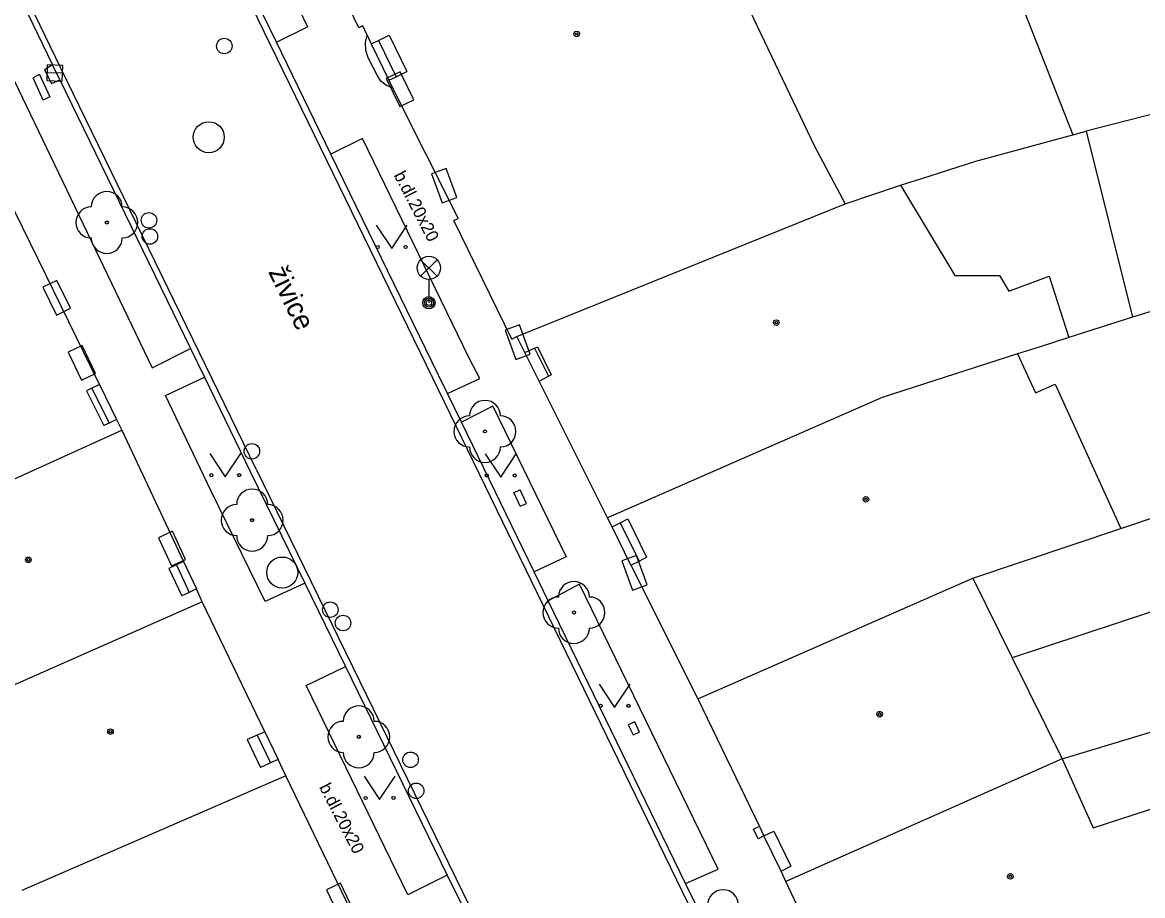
# Model space of a CAD drawing. Extents: x -595546 to -593986, y -1160845 to -1159202.
# Drawn here: x -595474.42 to -595438.29, y -1160132.09 to -1160103.93 of the extents above; entities that cross this region are included whole.
import ezdxf

# ---------------------------------------------------------------- set-up
doc = ezdxf.new("R2010")
doc.units = 0
for name, color, linetype in [('DOP - rozhrani ploch obecne', 7, 'Continuous'), ('Level 22', 7, 'Continuous'), ('Level 24', 7, 'Continuous'), ('Level 27', 7, 'Continuous'), ('Level 28', 7, 'Continuous'), ('Level 31', 7, 'Continuous'), ('Level 33', 7, 'Continuous'), ('Level 36', 7, 'Continuous'), ('Level 39', 7, 'Continuous'), ('silnoproud - povrch.  znaky a  RIS  skut. velikost', 7, 'Continuous'), ('slaboproud - povrch.  znaky a tel. budka skut. velikost', 7, 'Continuous'), ('TM - budovy zdene_ betonove - NP', 7, 'Continuous'), ('TM - budovy zdene_ betonove - VP', 7, 'Continuous'), ('TM - chodniky - VP', 7, 'Continuous'), ('TM - komunikace - VP', 7, 'Continuous'), ('TM - letecke snimky - pomocna linie', 7, 'Continuous'), ('TM - pomocna konstrukcni linie', 7, 'Continuous'), ('TM - popis povrchu', 7, 'Continuous'), ('TM - rozhrani mezi zpev. plochami mezi sebou - VP', 7, 'Continuous'), ('TM - rozhrani ploch obecne - VP', 7, 'Continuous'), ('TM - schody - NP', 7, 'Continuous'), ('TM - vstup do budovy - zdene_ betonove', 7, 'Continuous')]:
    doc.layers.add(name, color=color, linetype=linetype)

msp = doc.modelspace()

# ---------------------------------------------------------------- linework, layer by layer
at = {"layer": 'DOP - rozhrani ploch obecne'}
for points in [[(-595432.28, -1160105.44), (-595438.3, -1160106.97), (-595440.11, -1160107.43)], [(-595440.54, -1160107.55), (-595440.11, -1160107.43)], [(-595440.11, -1160107.43), (-595438.61, -1160113.43)], [(-595443.67, -1160108.4), (-595440.54, -1160107.55)], [(-595446.09, -1160109.18), (-595445.41, -1160108.96), (-595443.67, -1160108.4)], [(-595437.7, -1160113.16), (-595438.61, -1160113.43)], [(-595438.61, -1160113.43), (-595440.66, -1160114.09)], [(-595438.99, -1160120.25), (-595435.12, -1160118.95)]]:
    msp.add_lwpolyline(points, dxfattribs=at)
at = {"layer": 'Level 22'}
for centre in [(-595471.7, -1160110.38), (-595459.5, -1160117.12), (-595467.01, -1160119.98), (-595456.63, -1160122.96), (-595463.57, -1160126.97)]:
    msp.add_circle(centre, 0.05, dxfattribs=at)
for centre, start, end in [((-595471.7, -1160109.88), 0, 180), ((-595472.2, -1160110.38), 90, 270), ((-595471.2, -1160110.38), 270, 90), ((-595471.7, -1160110.88), 180, 0), ((-595459.5, -1160116.62), 0, 180), ((-595460, -1160117.12), 90, 270), ((-595459, -1160117.12), 270, 90), ((-595459.5, -1160117.62), 180, 0), ((-595467.01, -1160119.48), 0, 180), ((-595467.51, -1160119.98), 90, 270), ((-595466.51, -1160119.98), 270, 90), ((-595467.01, -1160120.48), 180, 0), ((-595456.63, -1160122.46), 0, 180), ((-595457.13, -1160122.96), 90, 270), ((-595456.13, -1160122.96), 270, 90), ((-595456.63, -1160123.46), 180, 0), ((-595463.57, -1160126.47), 0, 180), ((-595464.07, -1160126.97), 90, 270), ((-595463.07, -1160126.97), 270, 90), ((-595463.57, -1160127.47), 180, 0), ((-595451.82, -1160132.4), 0, 180)]:
    msp.add_arc(centre, 0.5, start, end, dxfattribs=at)
at = {"layer": 'Level 24'}
for points in [[(-595462.686, -1160105.741), (-595462.249, -1160106.64), (-595461.799, -1160106.421), (-595462.237, -1160105.522)], [(-595461.221, -1160108.806), (-595460.879, -1160109.746), (-595460.409, -1160109.575), (-595460.751, -1160108.635)], [(-595472.872, -1160113.149), (-595473.31, -1160112.251), (-595473.76, -1160112.47), (-595473.321, -1160113.369)], [(-595458.851, -1160113.856), (-595458.509, -1160114.796), (-595458.039, -1160114.625), (-595458.381, -1160113.685)], [(-595472.943, -1160114.567), (-595472.513, -1160115.47), (-595472.062, -1160115.255), (-595472.492, -1160114.352)], [(-595469.158, -1160121.245), (-595469.584, -1160120.34), (-595470.036, -1160120.553), (-595469.611, -1160121.458)], [(-595455.081, -1160121.296), (-595454.739, -1160122.236), (-595454.269, -1160122.065), (-595454.611, -1160121.125)], [(-595463.726, -1160132.593), (-595464.157, -1160131.69), (-595464.608, -1160131.905), (-595464.178, -1160132.808)]]:
    msp.add_lwpolyline(points, close=True, dxfattribs=at)
at = {"layer": 'Level 27'}
msp.add_line((-595473.13, -1160105.569), (-595473.63, -1160105.551), dxfattribs=at)
msp.add_lwpolyline([(-595473.121, -1160105.319), (-595473.621, -1160105.301), (-595473.639, -1160105.801), (-595473.139, -1160105.819)], close=True, dxfattribs=at)
for centre in [(-595468.41, -1160107.63), (-595466.04, -1160121.67)]:
    msp.add_circle(centre, 0.5, dxfattribs=at)
at = {"layer": 'Level 28'}
for centre in [(-595470.34, -1160110.31), (-595470.31, -1160110.83), (-595467.02, -1160117.76), (-595464.49, -1160122.87), (-595464.08, -1160123.3), (-595461.9, -1160127.71), (-595461.72, -1160128.71)]:
    msp.add_circle(centre, 0.25, dxfattribs=at)
at = {"layer": 'Level 31'}
msp.add_circle((-595467.91, -1160104.69), 0.25, dxfattribs=at)
at = {"layer": 'Level 33'}
for p, q in [((-595461.575, -1160112.11), (-595461.045, -1160111.58)), ((-595461.575, -1160111.58), (-595461.045, -1160112.11)), ((-595461.31, -1160112.22), (-595461.31, -1160112.97))]:
    msp.add_line(p, q, dxfattribs=at)
for centre, radius in [((-595461.31, -1160111.845), 0.375), ((-595461.31, -1160112.97), 0.2), ((-595461.31, -1160112.97), 0.145), ((-595461.31, -1160112.97), 0.0876)]:
    msp.add_circle(centre, radius, dxfattribs=at)
at = {"layer": 'Level 36'}
for points in [[(-595463.01, -1160110.47), (-595462.51, -1160111.22), (-595462.01, -1160110.47)], [(-595468.38, -1160117.83), (-595467.88, -1160118.58), (-595467.38, -1160117.83)], [(-595459.49, -1160117.84), (-595458.99, -1160118.59), (-595458.49, -1160117.84)], [(-595455.82, -1160125.27), (-595455.32, -1160126.02), (-595454.82, -1160125.27)], [(-595463.4, -1160128.24), (-595462.9, -1160128.99), (-595462.4, -1160128.24)]]:
    msp.add_lwpolyline(points, dxfattribs=at)
for centre in [(-595462.96, -1160111.17), (-595462.061, -1160111.17), (-595468.33, -1160118.53), (-595467.431, -1160118.53), (-595459.44, -1160118.54), (-595458.541, -1160118.54), (-595455.77, -1160125.97), (-595454.871, -1160125.97), (-595463.35, -1160128.94), (-595462.451, -1160128.94)]:
    msp.add_circle(centre, 0.05, dxfattribs=at)
at = {"layer": 'Level 39'}
for centre, radius in [((-595456.54, -1160104.3), 0.09), ((-595456.54, -1160104.3), 0.0398), ((-595450.1, -1160113.61), 0.09), ((-595450.1, -1160113.61), 0.0398), ((-595447.21, -1160119.31), 0.09), ((-595447.21, -1160119.31), 0.0398), ((-595474.23, -1160121.26), 0.09), ((-595474.23, -1160121.26), 0.0398), ((-595446.77, -1160126.24), 0.09), ((-595446.77, -1160126.24), 0.0398), ((-595471.58, -1160126.8), 0.09), ((-595471.58, -1160126.8), 0.0398), ((-595442.55, -1160131.47), 0.09), ((-595442.55, -1160131.47), 0.0398)]:
    msp.add_circle(centre, radius, dxfattribs=at)
at = {"layer": 'silnoproud - povrch.  znaky a  RIS  skut. velikost'}
for points in [[(-595458.57, -1160119.09), (-595458.36, -1160119)], [(-595458.16, -1160119.44), (-595458.36, -1160119)], [(-595458.37, -1160119.53), (-595458.57, -1160119.09)], [(-595458.37, -1160119.53), (-595458.16, -1160119.44)], [(-595450.64, -1160129.86), (-595450.84, -1160129.95)], [(-595450.69, -1160130.26), (-595450.84, -1160129.95)], [(-595450.5, -1160130.16), (-595450.69, -1160130.26)]]:
    msp.add_lwpolyline(points, dxfattribs=at)
at = {"layer": 'slaboproud - povrch.  znaky a tel. budka skut. velikost'}
for points in [[(-595473.87, -1160105.61), (-595474.08, -1160105.71)], [(-595473.87, -1160105.61), (-595473.54, -1160106.33)], [(-595473.75, -1160106.43), (-595474.08, -1160105.71)], [(-595473.54, -1160106.33), (-595473.75, -1160106.43)], [(-595454.67, -1160126.49), (-595454.88, -1160126.58)], [(-595454.88, -1160126.58), (-595454.72, -1160126.91)], [(-595454.51, -1160126.82), (-595454.67, -1160126.49)], [(-595454.72, -1160126.91), (-595454.51, -1160126.82)]]:
    msp.add_lwpolyline(points, dxfattribs=at)
at = {"layer": 'TM - budovy zdene_ betonove - NP'}
for points in [[(-595463.17, -1160104.62), (-595462.93, -1160104.51), (-595462.59, -1160104.34)], [(-595462.59, -1160104.34), (-595462.02, -1160105.51)], [(-595462.6, -1160105.79), (-595462.36, -1160105.68), (-595462.02, -1160105.51)], [(-595458.21, -1160114.57), (-595457.9, -1160114.43), (-595457.81, -1160114.39)], [(-595457.81, -1160114.39), (-595457.36, -1160115.29)], [(-595457.75, -1160115.5), (-595457.45, -1160115.34), (-595457.36, -1160115.29)], [(-595471.94, -1160115.61), (-595472.18, -1160115.72), (-595472.36, -1160115.81)], [(-595472.36, -1160115.81), (-595471.8, -1160116.93)], [(-595471.39, -1160116.74), (-595471.62, -1160116.85), (-595471.8, -1160116.93)], [(-595455.4, -1160120.2), (-595455.14, -1160120.07), (-595454.89, -1160119.94)], [(-595454.89, -1160119.94), (-595454.29, -1160121.18)], [(-595454.79, -1160121.43), (-595454.53, -1160121.3), (-595454.29, -1160121.18)], [(-595469.23, -1160121.31), (-595469.45, -1160121.42), (-595469.7, -1160121.54)], [(-595469.7, -1160121.54), (-595469.28, -1160122.42)], [(-595468.81, -1160122.2), (-595469.04, -1160122.31), (-595469.28, -1160122.42)], [(-595466.6, -1160126.81), (-595466.85, -1160126.92), (-595467.17, -1160127.06)], [(-595467.17, -1160127.06), (-595466.74, -1160127.96)], [(-595466.17, -1160127.7), (-595466.42, -1160127.81), (-595466.74, -1160127.96)], [(-595450.5, -1160130.16), (-595450.18, -1160130.01)], [(-595450.18, -1160130.01), (-595449.63, -1160131.14)], [(-595449.95, -1160131.3), (-595449.63, -1160131.14)]]:
    msp.add_lwpolyline(points, dxfattribs=at)
at = {"layer": 'TM - budovy zdene_ betonove - VP'}
for points in [[(-595463.57, -1160104.1), (-595465.36, -1160100.37)], [(-595451.64, -1160102.1), (-595448.87, -1160107.92)], [(-595463.44, -1160104.04), (-595463.57, -1160104.1)], [(-595463.3, -1160104.34), (-595463.44, -1160104.04)], [(-595463.3, -1160104.34), (-595463.17, -1160104.62)], [(-595463.17, -1160104.62), (-595462.6, -1160105.79)], [(-595462.6, -1160105.79), (-595462.48, -1160106.04)], [(-595462.48, -1160106.04), (-595460.37, -1160110.25)], [(-595471.94, -1160115.61), (-595475.91, -1160107.5)], [(-595448.87, -1160107.92), (-595447.88, -1160109.78)], [(-595447.88, -1160109.78), (-595446.09, -1160109.18)], [(-595446.09, -1160109.18), (-595444.34, -1160112.09)], [(-595458.47, -1160114.06), (-595447.88, -1160109.78)], [(-595460.5, -1160110.32), (-595460.37, -1160110.25)], [(-595458.63, -1160114.14), (-595460.5, -1160110.32)], [(-595444.34, -1160112.09), (-595442.9, -1160112.09)], [(-595442.9, -1160112.09), (-595442.6, -1160112.6)], [(-595442.6, -1160112.6), (-595441.3, -1160112.11)], [(-595441.3, -1160112.11), (-595440.66, -1160114.09)], [(-595458.63, -1160114.14), (-595458.47, -1160114.06)], [(-595458.21, -1160114.57), (-595458.47, -1160114.06)], [(-595440.66, -1160114.09), (-595441.62, -1160114.4)], [(-595442.32, -1160114.62), (-595446.69, -1160116.03)], [(-595441.62, -1160114.4), (-595442.32, -1160114.62)], [(-595442.32, -1160114.62), (-595441.74, -1160115.88)], [(-595455.55, -1160119.91), (-595457.75, -1160115.5)], [(-595441.74, -1160115.88), (-595441.11, -1160115.6)], [(-595441.11, -1160115.6), (-595438.99, -1160120.25)], [(-595446.69, -1160116.03), (-595455.55, -1160119.91)], [(-595471.39, -1160116.74), (-595471.22, -1160117.08)], [(-595479.81, -1160120.97), (-595471.22, -1160117.08)], [(-595471.22, -1160117.08), (-595469.23, -1160121.31)], [(-595455.4, -1160120.2), (-595455.55, -1160119.91)], [(-595443.76, -1160121.85), (-595438.99, -1160120.25)], [(-595431.22, -1160120.7), (-595442.49, -1160124.42)], [(-595454.79, -1160121.43), (-595452.63, -1160125.74)], [(-595452.63, -1160125.74), (-595443.76, -1160121.85)], [(-595443.76, -1160121.85), (-595442.49, -1160124.42)], [(-595468.62, -1160122.62), (-595468.81, -1160122.2)], [(-595468.62, -1160122.62), (-595477.19, -1160126.4)], [(-595466.6, -1160126.81), (-595468.62, -1160122.62)], [(-595442.49, -1160124.42), (-595440.88, -1160127.68)], [(-595452.63, -1160125.74), (-595450.64, -1160129.86)], [(-595440.88, -1160127.68), (-595434.69, -1160125.81)], [(-595465.92, -1160128.23), (-595466.17, -1160127.7)], [(-595440.88, -1160127.68), (-595449.79, -1160131.64)], [(-595440.88, -1160127.68), (-595439.88, -1160129.9)], [(-595465.92, -1160128.23), (-595474.44, -1160131.93)], [(-595463.82, -1160132.59), (-595465.92, -1160128.23)], [(-595450.64, -1160129.86), (-595450.5, -1160130.16)], [(-595449.79, -1160131.64), (-595449.95, -1160131.3)], [(-595447.68, -1160136.1), (-595447.78, -1160135.89), (-595449.79, -1160131.64)]]:
    msp.add_lwpolyline(points, dxfattribs=at)
at = {"layer": 'TM - chodniky - VP'}
for points in [[(-595471.93, -1160092.88), (-595470.88, -1160092.4), (-595468.58, -1160097.11), (-595465.22, -1160104.07)], [(-595478.75, -1160097.4), (-595476.94, -1160101.14), (-595470.24, -1160115.07)], [(-595466.23, -1160104.57), (-595465.22, -1160104.07)], [(-595463.45, -1160107.67), (-595464.47, -1160108.18)], [(-595459.67, -1160115.41), (-595460.01, -1160114.76), (-595463.45, -1160107.67)], [(-595470.24, -1160115.07), (-595469, -1160114.44)], [(-595465.31, -1160122.01), (-595466.59, -1160122.61), (-595468.34, -1160119.02), (-595469.81, -1160115.96), (-595468.55, -1160115.37)], [(-595460.71, -1160115.9), (-595459.67, -1160115.41)], [(-595459.25, -1160116.3), (-595460.26, -1160116.82)], [(-595459.25, -1160116.3), (-595456.88, -1160121.16), (-595457.91, -1160121.65)], [(-595456.45, -1160122.05), (-595457.46, -1160122.58)], [(-595451.98, -1160131.24), (-595456.45, -1160122.05)], [(-595465.27, -1160125.31), (-595464, -1160124.7)], [(-595461.99, -1160132.07), (-595465.27, -1160125.31)], [(-595453.03, -1160131.7), (-595451.98, -1160131.24)], [(-595460.72, -1160131.43), (-595461.99, -1160132.07)]]:
    msp.add_lwpolyline(points, dxfattribs=at)
at = {"layer": 'TM - komunikace - VP'}
for points in [[(-595466.23, -1160104.57), (-595469.65, -1160097.55), (-595471.93, -1160092.88)], [(-595477.55, -1160096.87), (-595475.67, -1160100.73), (-595473.45, -1160105.3)], [(-595464.47, -1160108.18), (-595466.23, -1160104.57)], [(-595473.45, -1160105.3), (-595473.71, -1160105.46), (-595473.48, -1160105.9), (-595473.22, -1160105.78)], [(-595473.22, -1160105.78), (-595469, -1160114.44)], [(-595460.71, -1160115.9), (-595461, -1160115.31), (-595464.47, -1160108.18)], [(-595469, -1160114.44), (-595468.55, -1160115.37)], [(-595468.55, -1160115.37), (-595467.06, -1160118.43), (-595465.31, -1160122.01)], [(-595460.26, -1160116.82), (-595460.71, -1160115.9)], [(-595457.91, -1160121.65), (-595460.26, -1160116.82)], [(-595457.46, -1160122.58), (-595457.91, -1160121.65)], [(-595465.31, -1160122.01), (-595464, -1160124.7)], [(-595453.03, -1160131.7), (-595457.46, -1160122.58)], [(-595464, -1160124.7), (-595460.72, -1160131.43)], [(-595460.72, -1160131.43), (-595460.27, -1160132.35)], [(-595452.57, -1160132.64), (-595453.03, -1160131.7)]]:
    msp.add_lwpolyline(points, dxfattribs=at)
at = {"layer": 'TM - letecke snimky - pomocna linie'}
for points in [[(-595450.21, -1160097.77), (-595449.14, -1160100.78), (-595443.91, -1160098.96), (-595440.54, -1160107.55)], [(-595439.88, -1160129.9), (-595434.65, -1160128.21), (-595434.38, -1160128.96)]]:
    msp.add_lwpolyline(points, dxfattribs=at)
at = {"layer": 'TM - pomocna konstrukcni linie'}
msp.add_lwpolyline([(-595473.22, -1160105.78), (-595473.45, -1160105.3)], dxfattribs=at)
at = {"layer": 'TM - rozhrani mezi zpev. plochami mezi sebou - VP'}
for points in [[(-595473.19, -1160105.38), (-595475.49, -1160100.64), (-595484.13, -1160082.89), (-595487.98, -1160074.96)], [(-595461.18, -1160115.4), (-595469.83, -1160097.64)], [(-595466.88, -1160118.34), (-595473.19, -1160105.38)], [(-595443.38, -1160152.01), (-595461.18, -1160115.4)], [(-595466.88, -1160118.34), (-595458.23, -1160136.06), (-595453.06, -1160146.74)]]:
    msp.add_lwpolyline(points, dxfattribs=at)
at = {"layer": 'TM - rozhrani ploch obecne - VP'}
for points in [[(-595463.27, -1160105.07), (-595463.34, -1160104.83), (-595463.35, -1160104.58), (-595463.3, -1160104.34)], [(-595462.98, -1160105.63), (-595463.27, -1160105.07)], [(-595462.48, -1160106.04), (-595462.68, -1160105.96), (-595462.86, -1160105.82), (-595462.98, -1160105.63)]]:
    msp.add_lwpolyline(points, dxfattribs=at)
at = {"layer": 'TM - schody - NP'}
for points in [[(-595462.93, -1160104.51), (-595462.36, -1160105.68)], [(-595457.9, -1160114.43), (-595457.45, -1160115.34)], [(-595472.18, -1160115.72), (-595471.62, -1160116.85)], [(-595455.14, -1160120.07), (-595454.53, -1160121.3)], [(-595469.45, -1160121.42), (-595469.04, -1160122.31)], [(-595466.85, -1160126.92), (-595466.42, -1160127.81)]]:
    msp.add_lwpolyline(points, dxfattribs=at)
at = {"layer": 'TM - vstup do budovy - zdene_ betonove'}
for points in [[(-595457.75, -1160115.5), (-595458.21, -1160114.57)], [(-595471.94, -1160115.61), (-595471.39, -1160116.74)], [(-595454.79, -1160121.43), (-595455.4, -1160120.2)], [(-595469.23, -1160121.31), (-595468.81, -1160122.2)], [(-595466.6, -1160126.81), (-595466.17, -1160127.7)], [(-595449.95, -1160131.3), (-595450.5, -1160130.16)]]:
    msp.add_lwpolyline(points, dxfattribs=at)

# ---------------------------------------------------------------- texts
at = {"layer": 'TM - popis povrchu'}
for s, height, rotation, p in [('b.dl.20x20', 0.4, 297.3424, (-595462.45, -1160108.85)), ('živice', 0.65, 295.9857, (-595466.5, -1160111.97)), ('b.dl.20x20', 0.4, 297.3424, (-595464.86, -1160128.59))]:
    msp.add_text(s, height=height, rotation=rotation, dxfattribs=at).set_placement(p)

doc.saveas('drawing.dxf')
